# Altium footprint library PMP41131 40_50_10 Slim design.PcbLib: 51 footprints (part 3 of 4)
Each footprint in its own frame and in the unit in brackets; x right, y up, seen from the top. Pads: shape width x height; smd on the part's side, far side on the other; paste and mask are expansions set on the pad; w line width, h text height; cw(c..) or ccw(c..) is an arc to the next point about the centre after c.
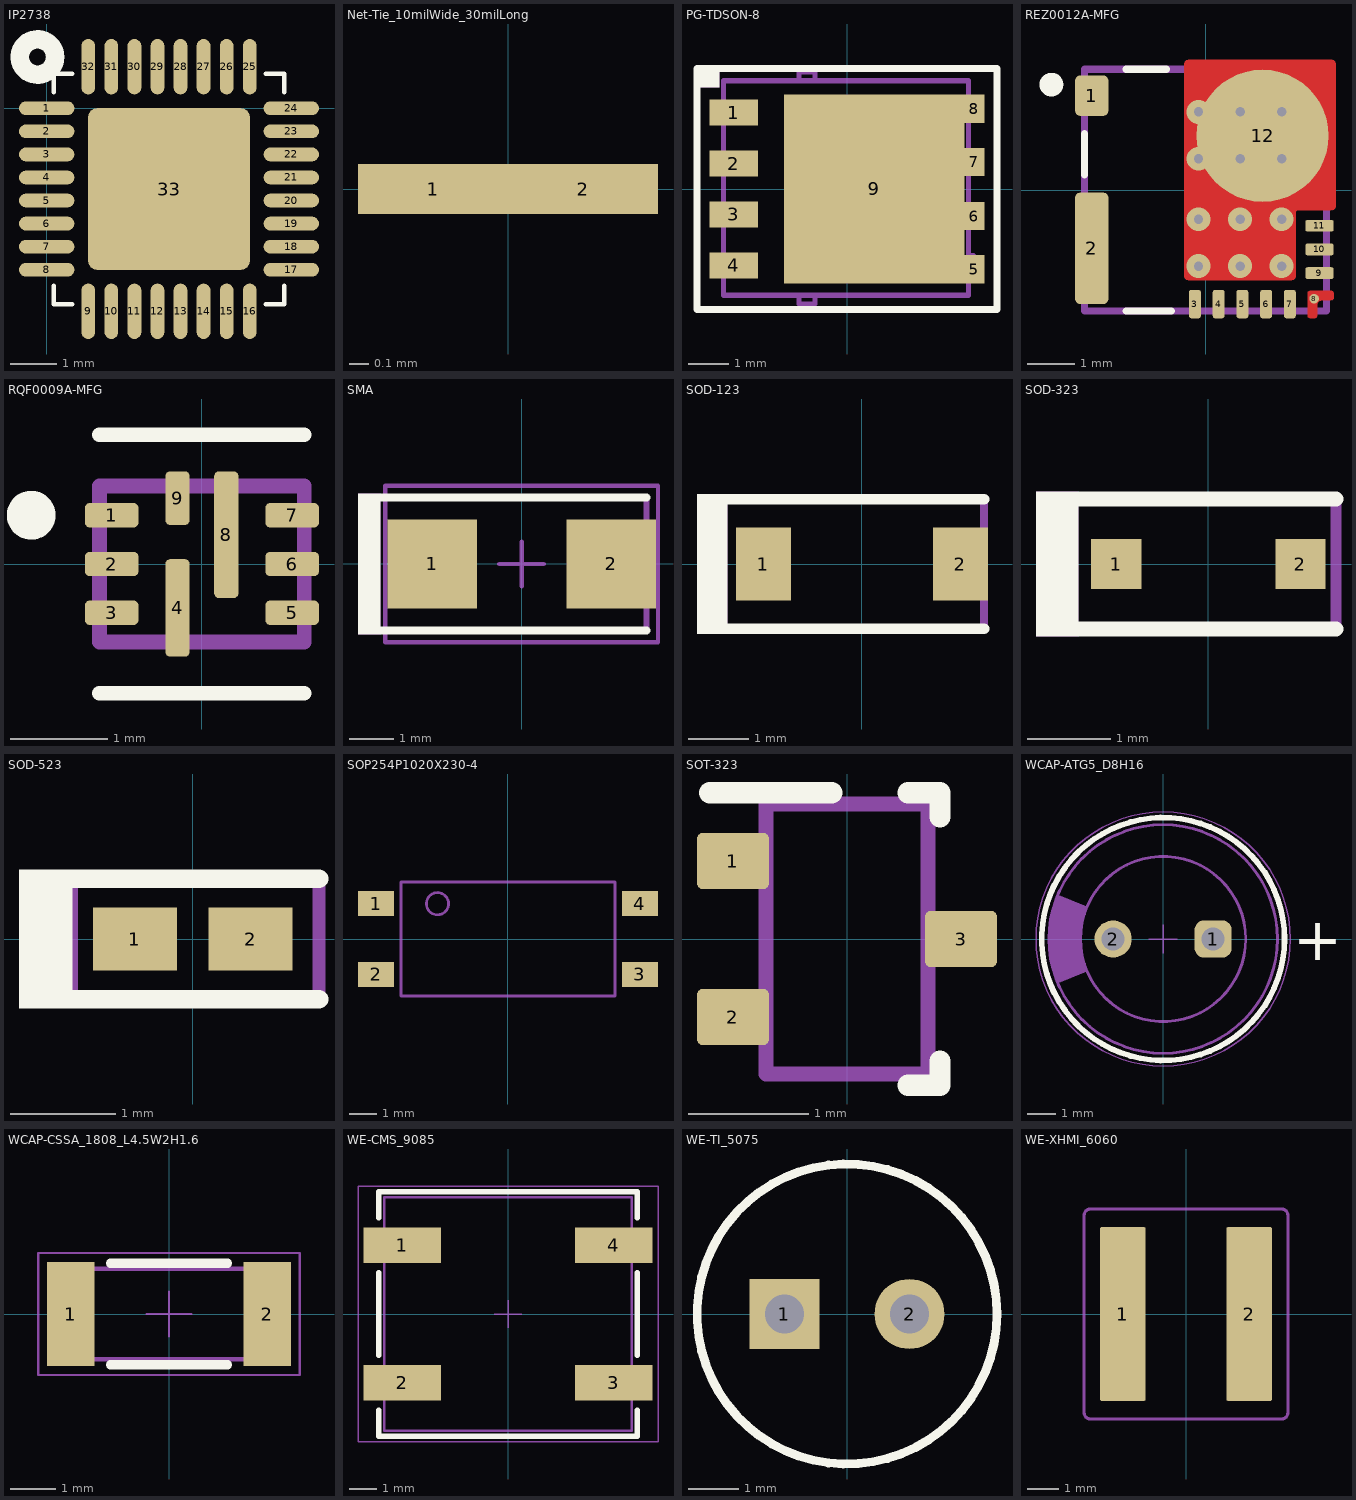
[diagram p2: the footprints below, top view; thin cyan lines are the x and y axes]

## IP2738 [mm]
height 1.1
pads (33):
  oval 1.2x0.3 smd: 1(0,0) 2(0,-0.5) 3(0,-1) 4(0,-1.5) 5(0,-2) 6(0,-2.5) 7(0,-3) 8(0,-3.5) 17(5.3,-3.5) 18(5.3,-3) 19(5.3,-2.5) 20(5.3,-2) 21(5.3,-1.5) 22(5.3,-1) 23(5.3,-0.5) 24(5.3,0)
  oval 0.3x1.2 smd: 9(0.9,-4.4) 10(1.4,-4.4) 11(1.9,-4.4) 12(2.4,-4.4) 13(2.9,-4.4) 14(3.4,-4.4) 15(3.9,-4.4) 16(4.4,-4.4) 25(4.4,0.9) 26(3.9,0.9) 27(3.4,0.9) 28(2.9,0.9) 29(2.4,0.9) 30(1.9,0.9) 31(1.4,0.9) 32(0.9,0.9)
  rrect10% 3.5x3.5 smd: 33(2.65,-1.75)
Top Overlay:
  circle w0.4: c-0.2,1.11 r0.382
  lines w0.1: 0.15,-3.85 0.15,-4.25 0.55,-4.25 ; 0.15,0.35 0.15,0.75 0.55,0.75 ; 4.75,-4.25 5.15,-4.25 5.15,-3.85 ; 4.75,0.75 5.15,0.75 5.15,0.35
Mechanical 5:
  text ".Designator" at -1.7,3 h1.02

## Net-Tie_10milWide_30milLong [mil] "10mil net tie, no solder mask opening, no solder paste"
height 43.31
pads (2):
  rect 30x10 smd paste-5 mask-5: 1(-15,0) 2(15,0)

## PG-TDSON-8 [mm] "Infineon recommended land pattern"
height 1.1
pads (9):
  rect 1.2x0.65 smd: 1(-2.825,1.905) 2(-2.825,0.635) 3(-2.825,-0.635) 4(-2.825,-1.905)
  rect 0.5x0.7 smd: 5(3.175,-2) 6(3.175,-0.675) 7(3.175,0.675) 8(3.175,2)
  rect 4.5x4.7 smd paste-2.25: 9(0.675,0)
Top Overlay:
  rectangle: -3.74,2.528 -3.175,2.975
  lines w0.178: -3.74,-3 -0.105,-3 3.74,-3 3.74,0 3.74,3 0.105,3 -3.74,3 -3.74,0 -3.74,-3
Top Paste:
  rectangle: -1.475,-2.25 -0.242,-0.95
  rectangle: 0.058,-2.25 1.291,-0.95
  rectangle: 1.591,-2.25 2.824,-0.95
  rectangle: 1.591,-0.65 2.824,0.65
  rectangle: 0.058,-0.65 1.291,0.65
  rectangle: -1.475,-0.65 -0.242,0.65
  rectangle: 1.591,0.95 2.824,2.25
  rectangle: 0.058,0.95 1.291,2.25
  rectangle: -1.475,0.95 -0.242,2.25
Mechanical 5:
  rectangle: -3.74,2.528 -3.175,2.975
  lines w0.127: -3.075,-2.1 -3.2,-2.1 -3.2,-1.66 -3.075,-1.66 ; -3.075,-0.83 -3.2,-0.83 -3.2,-0.39 -3.075,-0.39 ; -3.075,0.44 -3.2,0.44 -3.2,0.88 -3.075,0.88 ; -3.075,1.71 -3.2,1.71 -3.2,2.15 -3.075,2.15 ; -1.2,-2.65 -1.2,-2.87 -0.8,-2.87 -0.8,-2.65 ; -1.2,2.7 -1.2,2.92 -0.8,2.92 -0.8,2.7 ; 3.025,-2.1 3.15,-2.1 3.15,-1.66 3.025,-1.66 ; 3.025,-0.83 3.15,-0.83 3.15,-0.39 3.025,-0.39 ; 3.025,0.44 3.15,0.44 3.15,0.88 3.025,0.88 ; 3.025,1.71 3.15,1.71 3.15,2.15 3.025,2.15 ; -3.075,-2.65 -3.075,2.7 3.025,2.7 3.025,-2.65 -3.075,-2.65
  text ".Designator" at -1.925,-0.5 h1.02
3D body "PG-TDSON-8.stp": height 1.1, standoff 0, extent -3.175,-2.895 3.175,2.895

## REZ0012A-MFG [mm]
height 1.1
pads (12):
  rrect29% 0.7x0.85 smd paste-1000 mask-1000: 1(-2.4,1.993)
  rrect29% 0.7x2.35 smd paste-1000 mask-1000: 2(-2.4,-1.226)
  rrect40% 0.25x0.6 smd paste+0 mask+0: 3(-0.225,-2.4) 4(0.275,-2.4) 5(0.775,-2.4) 6(1.275,-2.4) 7(1.775,-2.4)
  round 0.202 smd paste+0 mask+0: 8(2.288,-2.288)
  rrect40% 0.6x0.25 smd paste+0 mask+0: 9(2.4,-1.749) 10(2.4,-1.249) 11(2.4,-0.749)
  round 2.788 smd paste-1000 mask-1000: 12(1.199,1.148)
via -0.15,-1.6 diameter 0.5 hole 0.2
via 0.725,-1.6 diameter 0.5 hole 0.2
via 1.6,-1.6 diameter 0.5 hole 0.2
via -0.15,-0.61 diameter 0.5 hole 0.2
via 0.725,-0.61 diameter 0.5 hole 0.2
via 1.6,-0.61 diameter 0.5 hole 0.2
via -0.15,0.66 diameter 0.5 hole 0.2
via 0.725,0.66 diameter 0.5 hole 0.2
via 1.6,0.66 diameter 0.5 hole 0.2
via 1.6,1.65 diameter 0.5 hole 0.2
via 0.725,1.65 diameter 0.5 hole 0.2
via -0.15,1.65 diameter 0.5 hole 0.2
Top Layer:
  region: 2.2,-2.7 2.19,-2.7 2.172,-2.692 2.158,-2.678 2.15,-2.66 2.15,-2.65 2.15,-2.174 2.15,-2.164 2.158,-2.146 2.172,-2.132 2.19,-2.124 2.2,-2.124 2.65,-2.124 2.66,-2.124 2.678,-2.132 2.692,-2.146 2.7,-2.164 2.7,-2.174 2.7,-2.274 2.7,-2.284 2.692,-2.302 2.678,-2.316 2.66,-2.324 2.65,-2.324 2.45,-2.324 2.43,-2.326 2.394,-2.341 2.367,-2.368 2.352,-2.404 2.35,-2.424 2.35,-2.65 2.35,-2.66 2.342,-2.678 2.328,-2.692 2.31,-2.7 2.3,-2.7
  region: -0.45,2.65 -0.45,2.67 -0.435,2.707 -0.407,2.735 -0.37,2.75 -0.35,2.75 2.648,2.75 2.668,2.75 2.705,2.735 2.733,2.707 2.748,2.67 2.748,2.65 2.748,-0.325 2.748,-0.345 2.733,-0.382 2.705,-0.41 2.668,-0.425 2.648,-0.425 1.95,-0.425 1.94,-0.426 1.922,-0.433 1.908,-0.447 1.901,-0.465 1.9,-0.475 1.9,-1.8 1.9,-1.82 1.885,-1.857 1.857,-1.885 1.82,-1.9 1.8,-1.9 -0.35,-1.9 -0.37,-1.9 -0.407,-1.885 -0.435,-1.857 -0.45,-1.82 -0.45,-1.8
Top Overlay:
  circle w0.25: c-3.25,2.225 r0.125
  lines w0.15: -2.55,0.324 -2.55,1.193 ; -1.675,-2.55 -0.725,-2.55 ; -1.675,2.55 -0.825,2.55
Top Paste:
  drawing of 20 lines, arcs and shapes, not listed
Top Solder:
  drawing of 4 lines, arcs and shapes, not listed
Mechanical 5:
  lines w0.15: -2.55,-2.55 -2.55,2.55 2.55,2.55 2.55,-2.55 -2.55,-2.55
  text ".Designator" at 0.049,0.242 h0.5
3D body "IC_UCG28682_VQFN12.STEP": height 0.25, standoff 0, extent -2.85,-2.8 2.848,2.85

## RQF0009A-MFG [mm]
height 1.1
pads (9):
  rrect40% 0.55x0.25 smd paste+0 mask+0: 1(-0.925,0.5) 2(-0.925,0) 3(-0.925,-0.5) 5(0.925,-0.5) 6(0.925,0) 7(0.925,0.5)
  rrect40% 0.25x1 smd paste+0 mask+0: 4(-0.25,-0.45)
  rrect40% 0.25x1.3 smd paste+0 mask+0: 8(0.25,0.3)
  rrect40% 0.25x0.55 smd paste+0 mask+0: 9(-0.25,0.675)
Top Overlay:
  circle w0.25: c-1.75,0.5 r0.125
  lines w0.15: -1.05,-1.325 1.05,-1.325 ; -1.05,1.325 1.05,1.325
Mechanical 5:
  lines w0.15: -1.05,-0.8 1.05,-0.8 1.05,0.8 -1.05,0.8 -1.05,-0.8
  text ".Designator" at 0.05,0.217 h0.5
3D body "IC_TPS54538RQF_VQFN-HR9.STEP": height 0.25, standoff 0, extent -1.3,-1.05 1.3,1.05

## SMA [mm] "Molded Diode, 2-Leads, Body 4.3x2.6mm, IPC Medium Density, based on OnSemi component dimensions and land pattern"
height 2.27
pads (2):
  rect 2x2 smd: 1(-2,0) 2(2,0)
Top Overlay:
  rectangle: -3.658,-1.575 -3.15,1.575
  lines w0.178: -3.327,-1.486 2.794,-1.486 ; -3.327,1.486 2.794,1.486
Mechanical 5:
  rectangle: -3.658,-1.575 -3.15,1.575
  lines w0.127: -3.327,-1.486 2.794,-1.486 2.794,1.486 -3.327,1.486
  text ".Designator" at -2.769,-0.33 h1.02
Mechanical 15:
  lines w0.1: -0.5,0 0.5,0 ; 0,-0.5 0,0.5 ; -3.05,-1.75 3.05,-1.75 3.05,1.75 -3.05,1.75 -3.05,-1.75
3D body "SMA_nominal.stp": height 2.42, standoff 0.02, extent -2.6,-1.3 2.6,1.3

## SOD-123 [mm] "On Semi recommended land pattern"
height 1.35
pads (2):
  rect 0.915x1.22 smd: 1(-1.637,0) 2(1.637,0)
Top Overlay:
  rectangle: -2.743,-1.168 -2.235,1.168
  lines w0.178: -2.413,-1.079 2.032,-1.079 ; -2.413,1.079 2.032,1.079
Mechanical 5:
  rectangle: -2.743,-1.168 -2.235,1.168
  lines w0.127: -2.413,-1.079 2.032,-1.079 2.032,1.079 -2.413,1.079
  text ".Designator" at -1.956,-0.33 h0.76
3D body "SOD-123.stp": height 1.35, standoff 0, extent -1.932,-0.9 1.932,0.9

## SOD-323 [mm] "NXP recommended land pattern"
height 1.15
pads (2):
  rect 0.6x0.6 smd paste-0.05: 1(-1.1,0) 2(1.1,0)
Top Overlay:
  rectangle: -2.057,-0.864 -1.549,0.864
  lines w0.178: -1.803,-0.775 0.1,-0.775 1.525,-0.775 ; -1.803,0.775 0.1,0.775 1.525,0.775
Mechanical 5:
  rectangle: -2.057,-0.864 -1.549,0.864
  lines w0.127: -1.803,-0.775 0.1,-0.775 1.525,-0.775 1.525,0.775 0.1,0.775 -1.803,0.775
  text ".Designator" at -1.4,-0.275 h0.76
3D body "SOD-323.stp": height 1.1, standoff 0, extent -1.3,-0.675 1.3,0.675

## SOD-523 [mm] "NXP Semiconductor recommended land pattern, nominal STEP model"
height 0.7
pads (2):
  rect 0.8x0.6 smd paste-0.05: 1(-0.55,0) 2(0.55,0)
Top Overlay:
  rectangle: -1.651,-0.66 -1.143,0.66
  lines w0.178: -1.475,-0.572 0,-0.572 1.2,-0.572 ; -1.475,0.572 0,0.572 1.2,0.572
Mechanical 5:
  rectangle: -1.6,-0.635 -1.092,0.635
  lines w0.127: -1.475,-0.546 0,-0.546 1.2,-0.546 1.2,0.546 0,0.559 -1.475,0.559
  text ".Designator" at -0.991,-0.279 h0.56
3D body "SOD-523F.stp": height 0.72, standoff 0.02, extent -0.8,-0.399 0.8,0.399

## SOP254P1020X230-4 [mm] "VISHAY"
height 2
pads (4):
  rect 1.3x0.9 smd: 1(-4.75,1.27) 2(-4.75,-1.27) 3(4.75,-1.27) 4(4.75,1.27)
Mechanical 5:
  circle w0.1: c-2.54,1.27 r0.4
  lines w0.1: -3.85,-2.05 -3.85,2.05 3.85,2.05 3.85,-2.05 -3.85,-2.05
  text ".Designator" at -1.6,-0.3 h0.8
3D body: height 2, standoff 0, extent -3.849,-2.049 3.849,2.049
3D body: height 2.02, standoff 0, extent -2.939,0.871 -2.141,1.669

## SOT-323 [mm] "Diodes Inc recommended land pattern.  2016-02-24"
height 1.1
pads (3):
  rrect21% 0.6x0.47 smd: 1(-0.95,0.65) 2(-0.95,-0.65) 3(0.95,0)
Top Overlay:
  lines w0.178: -1.143,1.219 -0.127,1.219 ; 0.508,-1.219 0.775,-1.219 0.775,-1.016 ; 0.508,1.219 0.775,1.219 0.775,1.016
Mechanical 5:
  lines w0.127: -1.125,-0.8 -0.975,-0.8 -0.935,-0.8 -0.884,-0.8 -0.725,-0.8 -0.675,-0.8 -0.675,-0.5 -0.725,-0.5 -0.884,-0.5 -0.935,-0.5 -0.975,-0.5 -1.125,-0.5 -1.125,-0.8 ; -1.125,0.5 -0.975,0.5 -0.935,0.5 -0.884,0.5 -0.725,0.5 -0.675,0.5 -0.675,0.8 -0.725,0.8 -0.884,0.8 -0.935,0.8 -0.975,0.8 -1.125,0.8 -1.125,0.5 ; -0.675,-1.125 0.675,-1.125 0.675,1.125 -0.675,1.125 -0.675,-1.125 ; 0.675,-0.15 0.675,0.15 0.725,0.15 0.884,0.15 0.935,0.15 0.975,0.15 1.125,0.15 1.125,-0.15 0.975,-0.15 0.935,-0.15 0.884,-0.15 0.725,-0.15 0.675,-0.15
  text ".Designator" at -0.25,0.9 h0.8
3D body "SC-70.stp": height 1.13, standoff 0.02, extent -1.125,-1.125 1.125,1.125

## WCAP-ATG5_D8H16 [mm] "Aluminum Electrolytic Capacitors, 8x16mm"
height 16
pads (2):
  rrect50% 1.3x1.3 hole 0.8: 1(1.75,0)
  round 1.3 hole 0.8: 2(-1.75,0)
Top Overlay:
  circle w0.2: c0,0 r4.25
  text "+" at 4.55,-0.75 h1.5
Mechanical 3:
  text ".Designator" at -5.998,-0.4 h1.2
Mechanical 11:
  circle w0.1: c0,0 r4
  circle w0.1: c0,0 r2.89
  region: -3.685,-1.557 -3.762,-1.372 -3.881,-0.99 -3.96,-0.598 -4,-0.2 -4,0.2 -3.96,0.598 -3.881,0.99 -3.762,1.372 -3.685,1.557 -2.662,1.125 -2.662,1.124 -2.715,0.99 -2.8,0.714 -2.858,0.431 -2.886,0.144 -2.886,-0.144 -2.858,-0.431 -2.8,-0.714 -2.715,-0.99 -2.662,-1.124 -2.662,-1.125
Mechanical 15:
  circle w0.05: c0,0 r4.45
  lines w0.05: -0.5,0 0.5,0 ; 0,-0.5 0,0.5
3D body "8x16x3.5x0.5.stp": height 16.31, standoff -19.91, extent -3.99,-4 4,3.999

## WCAP-CSSA_1808_L4.5W2H1.6 [mm] "Ceramic Capacitors, body 4.50x2.00mm"
height 1.6
pads (2):
  rect 1.05x2.3 smd: 1(-2.175,0) 2(2.175,0)
Top Overlay:
  lines w0.2: -1.3,-1.125 1.3,-1.125 ; -1.3,1.125 1.3,1.125
Top Component Outline:
  lines w0.1: -2.25,-1 -2.25,1 2.25,1 2.25,-1 -2.25,-1
Top 3D Body:
  lines w0.1: -2.25,-1 -2.25,1 2.25,1 2.25,-1 -2.25,-1
Top Courtyard:
  lines w0.05: -2.9,-1.35 -2.9,1.35 2.9,1.35 2.9,-1.35 -2.9,-1.35
Top Component Center:
  lines w0.05: -0.5,0 0.5,0 ; 0,-0.5 0,0.5
Top Designator:
  text ".Designator" at -4.998,-0.333 h1
3D body "1808.step": height 1.6, standoff 0, extent -2.25,-1 2.25,1

## WE-CMS_9085 [mm] "Common Mode SMT Bead, body 9.00x8.50mm"
height 4.8
pads (4):
  rect 2.81x1.28 smd: 1(-3.85,2.5) 2(-3.85,-2.5) 3(3.85,-2.5) 4(3.85,2.5)
Top Overlay:
  lines w0.2: -4.7,-3.5 -4.7,-4.45 4.7,-4.45 4.7,-3.5 ; -4.7,-1.5 -4.7,1.5 ; -4.7,3.5 -4.7,4.45 4.7,4.45 4.7,3.5 ; 4.7,-1.5 4.7,1.5
Top Component Outline:
  lines w0.1: -4.5,-4.25 4.5,-4.25 4.5,4.25 -4.5,4.25 -4.5,-4.25
Top Courtyard:
  lines w0.05: -5.455,-4.65 -5.455,4.65 5.455,4.65 5.455,-4.65 -5.455,-4.65
Top Component Center:
  lines w0.05: -0.5,0 0.5,0 ; 0,-0.5 0,0.5
Top Designator:
  text ".Designator" at -7.498,-0.5 h1.5
3D body "Download_STP_WE-CMS-9085-7427523 (rev1).stp": height 4.63, standoff 0, extent -4.67,-4.25 4.67,4.25

## WE-TI_5075 [mm] "Wurth WE-TI 5075"
height 8.5
pads (2):
  rect 1.4x1.4 hole 0.787: 1(-1.25,0)
  round 1.4 hole 0.787: 2(1.25,0)
Top Overlay:
  circle w0.177: c0,0 r3
Mechanical 5:
  circle w0.1: c0,0 r3
  text ".Designator" at -1.992,-0.508 h1.02
3D body: height 8.5, standoff 0, extent -2.999,-2.999 2.999,2.999

## WE-XHMI_6060 [mm] "SMD, 2-Leads, Body 6.65x6.45mm"
height 6.1
pads (2):
  rrect7% 1.45x5.5 smd: 1(-2,0) 2(2,0)
Mechanical 5:
  lines w0.1: -3.225,-3.125 ccw(c-3.025,-3.125) -3.025,-3.325 3.025,-3.325 ccw(c3.025,-3.125) 3.225,-3.125 3.225,3.125 ccw(c3.025,3.125) 3.025,3.325 -3.025,3.325 ccw(c-3.025,3.125) -3.225,3.125 -3.225,-3.125
  text ".Designator" at -2,-0.7 h1.85
3D body "WE-XHMI_6060.stp": height 5.78, standoff -0.02, extent -3.225,-3.325 3.225,3.325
